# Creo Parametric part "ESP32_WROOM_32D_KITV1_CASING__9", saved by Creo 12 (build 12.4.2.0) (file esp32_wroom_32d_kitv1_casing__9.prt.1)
Units: Custom; MM, KILOGRAM, SECS

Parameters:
  PTC_WM_ITERATION = "0"
  PTC_WM_VERSION = "-.0"
  PTC_WM_LIFECYCLE_STATE = "In Work"
  PTC_WM_LIFECYCLE = "MO_CADDocument"
  PTC_WM_CREATED_BY = "Maximilian Roepper (Z0017RMS: MO)"
  PTC_WM_CREATED_ON = "18-Sep-26 11:36:42 AM"
  PTC_WM_MODIFIED_BY = "Maximilian Roepper (Z0017RMS: MO)"
  PTC_WM_MODIFIED_ON = "18-Sep-26 11:36:46 AM"
  PDMLINKNUMBER = "PDM000071454776"
  PTC_WM_NAME = "esp32_wroom_32d_kitv1_casing__9.prt"
  PTC_WM_NUMBER = "PDM000071454776"

Other parameters: WEIGHT, WEIGHT_FACTOR, WEIGHT_ADD, _MASS_TEMP, _DIFF_TEMP, MC_ERRORS, SUPPLIER

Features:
  1. coordinate system
  2. datum plane "PRT_YZ"
  3. datum plane "PRT_XY"
  4. datum plane "PRT_XZ"
  5. coordinate system
  6. datum axis
  7. datum axis
  8. datum axis
  9. coordinate system
  10. imported feature
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
Other named items: PRT, SIEMENS_MO, DRW_VIEW_ORG, PRT_X, PRT_Y, PRT_Z, CS0, ROUGH_GROB

Layers: 00_STD_CSYS-KSYS, 01_STD_PLANES-EBENEN, 02_STD_AXES-ACHSEN, 03_STD_CSYS-KSYS, 24_IMPORT_FEAT-IMPORT_KE

Surfaces: 5 plane, 1 cylinder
